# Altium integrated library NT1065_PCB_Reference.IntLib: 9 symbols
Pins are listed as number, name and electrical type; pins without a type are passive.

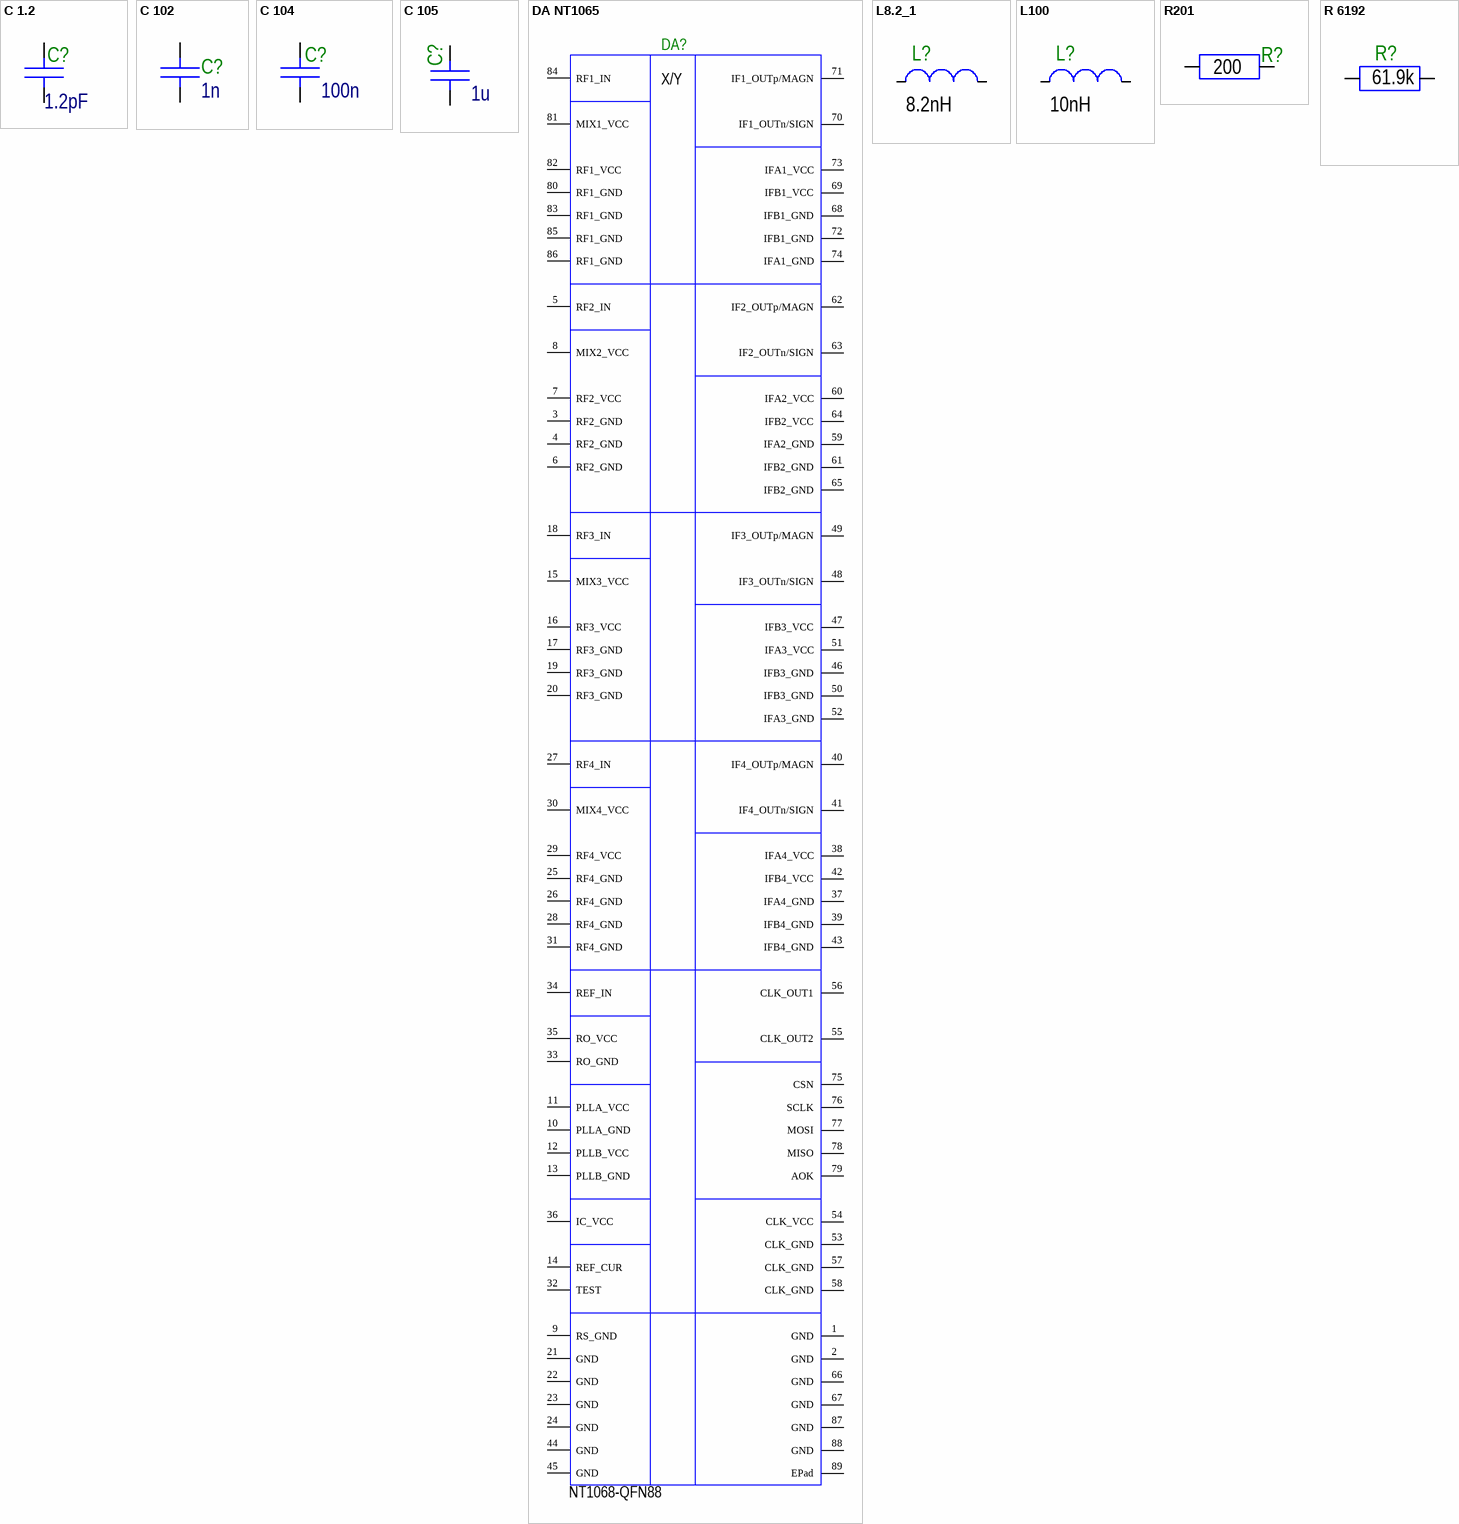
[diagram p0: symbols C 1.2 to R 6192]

## C 1.2
designator C?, comment 1.2pF
1.2pF, +-0.25pF, 50V, 0402, COG; PART_NUMBER: 0402N1R2C500N; PART_NAME: Hitano; Part_Label: 1.2пФ, +-0.25пФ, 50В, 0402, COG; Value: 1.2p
footprint 0402_C
pins: 1, 2

## C 102
designator C?, comment 1n
1nF, 5%, 25V, 0402, C0G; PART_NUMBER: GRM1555C1H102JA01D; PART_NAME: KEMET; Part_Label: 1нФ, 5%, 25В, 0402, C0G
footprint 0402_C
pins: 1, 2

## C 104
designator C?, comment 100n
0.1uF, 10%, 16V, 0402, X7R; PART_NUMBER: GRM155R71C104KA88D; PART_NAME: Murata; Part_Label: 0.1мкФ, 10%, 16В, 0402, X7R
footprint 0402_C
pins: 1, 2

## C 105
designator C?, comment 1u
1uF 10%, 10V, 0402, X5R; PART_NUMBER: GRM155R61A105K; PART_NAME: Murata; Part_Label: 1мкФ, 10%, 10В, 0402, X5R
footprint 0402_C
pins: 1, 2

## DA NT1065
designator DA?, comment NT1068-QFN88
RF Front-End, ADC, QFN88; Part_Label: IC, RF Front-End, ADC, QFN88; PART_NAME: NTL; IntHelpURL: \\dd\RF_departament\Datasheets\NT1065\NT1065.2\Datasheet\NT1065.2\SE\NT1065 SE DS v2.08.pdf
footprint QFN-88_NT1065 (Author : Golubev S.V.)
pins: 1 GND, 2 GND, 3 RF2_GND, 4 RF2_GND, 5 RF2_IN, 6 RF2_GND, 7 RF2_VCC, 8 MIX2_VCC, 9 RS_GND, 10 PLLA_GND, 11 PLLA_VCC, 12 PLLB_VCC, 13 PLLB_GND, 14 REF_CUR, 15 MIX3_VCC, 16 RF3_VCC, 17 RF3_GND, 18 RF3_IN, 19 RF3_GND, 20 RF3_GND, 21 GND, 22 GND, 23 GND, 24 GND, 25 RF4_GND, 26 RF4_GND, 27 RF4_IN, 28 RF4_GND, 29 RF4_VCC, 30 MIX4_VCC, 31 RF4_GND, 32 TEST, 33 RO_GND, 34 REF_IN, 35 RO_VCC, 36 IC_VCC, 37 IFA4_GND, 38 IFA4_VCC, 39 IFB4_GND, 40 IF4_OUTp/MAGN, 41 IF4_OUTn/SIGN, 42 IFB4_VCC, 43 IFB4_GND, 44 GND, 45 GND, 46 IFB3_GND, 47 IFB3_VCC, 48 IF3_OUTn/SIGN, 49 IF3_OUTp/MAGN, 50 IFB3_GND, 51 IFA3_VCC, 52 IFA3_GND, 53 CLK_GND, 54 CLK_VCC, 55 CLK_OUT2, 56 CLK_OUT1, 57 CLK_GND, 58 CLK_GND, 59 IFA2_GND, 60 IFA2_VCC, 61 IFB2_GND, 62 IF2_OUTp/MAGN, 63 IF2_OUTn/SIGN, 64 IFB2_VCC, 65 IFB2_GND, 66 GND, 67 GND, 68 IFB1_GND, 69 IFB1_VCC, 70 IF1_OUTn/SIGN, 71 IF1_OUTp/MAGN, 72 IFB1_GND, 73 IFA1_VCC, 74 IFA1_GND, 75 CSN, 76 SCLK, 77 MOSI, 78 MISO, 79 AOK, 80 RF1_GND, 81 MIX1_VCC, 82 RF1_VCC, 83 RF1_GND, 84 RF1_IN, 85 RF1_GND, 86 RF1_GND, 87 GND, 88 GND, 89 EPad

## L8.2_1
designator L?, comment 8.2nH
8.2nH, 2%, 0.54A, 0402; PART_NUMBER: LQW15AN8N2G00; Part_Label: 8.2нГ, 2%, 0.54А, 0402; PART_NAME: Murata; Part Number: L3.6; Всего приобретено: 100 шт.
footprint 0402_L
pins: 1, 2

## L100
designator L?, comment 10nH
10 nH, 2%, 0.54A, 0402; PART_NUMBER: LQW15AN10NG00; Part_Label: 10нГ, 2%, 0.54А, 0402; PART_NAME: Murata; Part Number: L3.6; Всего приобретено: 100 шт.
footprint 0402_L
pins: 1, 2

## R201
designator R?, comment 200
200 Ohm, 5%, 0402; PART_NAME: FaithfulLink; PART_NUMBER: RC0402J200R; Part_Label: 200 Ом, 5%, 0402
footprint 0402_R
pins: 1, 2

## R 6192
designator R?, comment 61.9k
61.9 kOhm, 1%, 0402; PART_NUMBER: RC0402FR-0761K9L; PART_NAME: FaithfulLink; Part_Label: 61.9 кОм, 1%, 0402
footprint 0402_R
pins: 1, 2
